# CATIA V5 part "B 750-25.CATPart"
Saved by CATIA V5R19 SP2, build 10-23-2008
Part number: B 750-25
Bounding box of the stored display mesh (mm): x -22.494 to 22.494, y -22.494 to 22.494, z 0 to 135
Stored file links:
  C:\Users\Bora\Desktop\3D Katı model\B serisi\B 750\B 750-25.CATPart
  C:\Program Files\Dassault Systemes\B19\intel_a\reffiles\standard\MetricThickPitch.txt
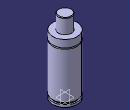
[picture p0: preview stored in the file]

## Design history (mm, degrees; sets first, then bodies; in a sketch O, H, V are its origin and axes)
Body1 (main body)
  Sketch1 on yz-plane, origin (0, 0, 0), H (0, 1, 0), V (0, 0, 1)
    point P3 (12, 134)
    point P5 (12, 134)
    point P7 (22.5, 94.5)
    point P8 (22.5, 92.5)
    point P12 (22.5, 92.5)
    point P13 (22.5, 94.5)
    line L1 (22.5, 0) -> (22.5, 4)
    line L2 (12, 134) -> (12, 108)
    arc A1 centre (11, 134) radius 1 from (12, 134) to (11, 135) ccw
    arc A2 centre (22.5, 93.5) radius 1 from (22.5, 94.5) to (22.5, 92.5) ccw
    line L3 (20, 7.5) -> (20, 4)
    line L4 (22.5, 7.5) -> (22.5, 92.5)
    line L5 (22.5, 94.5) -> (22.5, 108)
    line L6 (11, 135) -> (0, 135)
    point P15 (0, 135)
    line L7 (12, 108) -> (22.5, 108)
    line L8 (0, 0) -> (22.5, 0)
    line L9 (20, 7.5) -> (22.5, 7.5)
    line L10 (20, 4) -> (22.5, 4)
    coincidence: P15 V, P3 P5, P7 P13, P8 P12
    tangency: L6 A1
    horizontal: L7 H, L8 H, L9 H, L10 H
  Shaft1: profile Sketch1, axis Sketch1.V, angle 360
  Sketch2 on face of Shaft1 from Sketch1.L8, origin (0, 0, 0), H (1, 0, 0), V (0, -1, 0)
    point P1 (10, 0)
    distance P1 V = 10
  Hole1: placed by Sketch2, at (10, 0, 0) direction (0, 0, 1), diameter 6.647, depth 13, threaded "M8", thread diameter 8, thread depth 13, pitch 1.25
  CircPattern1: of Hole1, instances 2, angular step 180, axis from xy-plane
